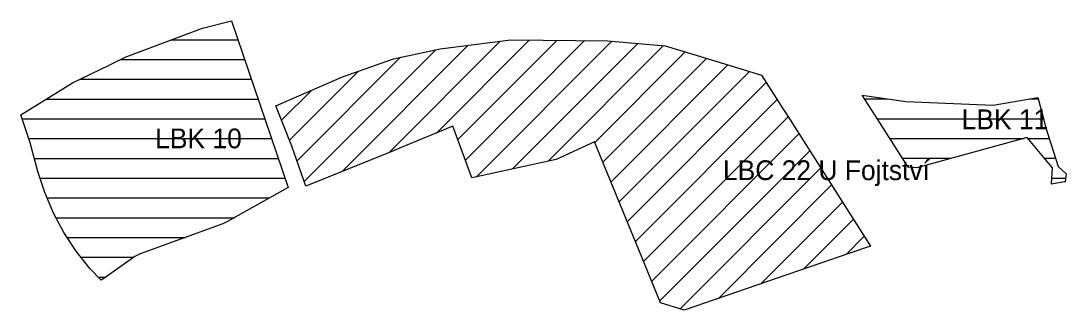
# Model space of a CAD drawing. Extents: x -477054 to -472307, y -1158904 to -1149471.
# Drawn here: x -476516 to -476092.7, y -1154894.3 to -1154777.4 of the extents above; entities that cross this region are included whole.
import ezdxf

# ---------------------------------------------------------------- set-up
doc = ezdxf.new("R2010")
doc.units = 0
doc.layers.add('16', color=7, linetype='Continuous')
doc.layers.add('19', color=7, linetype='Continuous')

msp = doc.modelspace()

# ---------------------------------------------------------------- linework, layer by layer
at = {"layer": '16'}
for p, q in [((-476454.84, -1154784.97), (-476428.16, -1154784.97)), ((-476385.77, -1154838.19), (-476334.82, -1154787.24)), ((-476366.82, -1154830.56), (-476321.87, -1154785.61)), ((-476347.69, -1154822.74), (-476310.09, -1154785.14)), ((-476339.04, -1154825.4), (-476298.88, -1154785.25)), ((-476335.99, -1154833.68), (-476287.68, -1154785.36)), ((-476331.41, -1154840.41), (-476276.6, -1154785.6)), ((-476316.95, -1154837.26), (-476266.19, -1154786.49)), ((-476302.49, -1154834.12), (-476255.77, -1154787.39)), ((-476475.57, -1154792.97), (-476425.43, -1154792.97)), ((-476404.15, -1154833.95), (-476362.28, -1154792.08)), ((-476401.22, -1154842.33), (-476347.93, -1154789.04)), ((-476283.61, -1154826.54), (-476246.98, -1154789.92)), ((-476280.31, -1154834.56), (-476238.3, -1154792.55)), ((-476277.01, -1154842.57), (-476229.62, -1154795.19)), ((-476492.11, -1154800.97), (-476422.69, -1154800.97)), ((-476407.17, -1154825.65), (-476379.22, -1154797.71)), ((-476273.71, -1154850.58), (-476220.94, -1154797.82)), ((-476410.38, -1154817.55), (-476398.29, -1154805.46)), ((-476270.41, -1154858.6), (-476214.13, -1154802.32)), ((-476505.64, -1154808.97), (-476419.96, -1154808.97)), ((-476267.11, -1154866.61), (-476209.72, -1154809.22)), ((-476174.31, -1154808.92), (-476165.01, -1154808.92)), ((-476107.36, -1154808.92), (-476103.97, -1154808.92)), ((-476515.47, -1154816.97), (-476417.23, -1154816.97)), ((-476263.8, -1154874.62), (-476205.31, -1154816.12)), ((-476169.19, -1154816.92), (-476101.86, -1154816.92)), ((-476512.85, -1154824.97), (-476414.49, -1154824.97)), ((-476260.5, -1154882.64), (-476200.89, -1154823.02)), ((-476164.08, -1154824.92), (-476109.68, -1154824.92)), ((-476108.14, -1154824.92), (-476099.51, -1154824.92)), ((-476257.2, -1154890.65), (-476196.48, -1154829.93)), ((-476510.56, -1154832.97), (-476411.76, -1154832.97)), ((-476158.97, -1154832.92), (-476139.04, -1154832.92)), ((-476101.46, -1154832.92), (-476096.99, -1154832.92)), ((-476249.04, -1154893.8), (-476192.07, -1154836.83)), ((-476508.23, -1154840.97), (-476409.03, -1154840.97)), ((-476233.51, -1154889.58), (-476187.66, -1154843.73)), ((-476098.49, -1154840.92), (-476092.85, -1154840.92)), ((-476505.41, -1154848.97), (-476415.26, -1154848.97)), ((-476216.27, -1154883.66), (-476183.25, -1154850.63)), ((-476501.78, -1154856.97), (-476429.5, -1154856.97)), ((-476199.04, -1154877.74), (-476178.83, -1154857.53)), ((-476497.23, -1154864.97), (-476449.49, -1154864.97)), ((-476181.8, -1154871.81), (-476174.42, -1154864.44)), ((-476491.61, -1154872.97), (-476470.28, -1154872.97)), ((-476484.68, -1154880.97), (-476481.64, -1154880.97))]:
    msp.add_line(p, q, dxfattribs=at)
msp.add_lwpolyline([(-476206.39, -1154814.43), (-476199.07, -1154825.88), (-476171.86, -1154868.44), (-476180.31, -1154871.3), (-476247.31, -1154894.32), (-476256.89, -1154891.41), (-476265.75, -1154869.9), (-476283.71, -1154826.29), (-476299.16, -1154833.39), (-476332.67, -1154840.68), (-476333.37, -1154840.83), (-476333.52, -1154840.41), (-476341.02, -1154820), (-476362.02, -1154828.63), (-476365.75, -1154830.13), (-476400.58, -1154844.16), (-476406.23, -1154828.01), (-476412.7, -1154811.69), (-476385.68, -1154800.01), (-476365.13, -1154792.68), (-476346.21, -1154788.68), (-476317.58, -1154785.07), (-476278.3, -1154785.45), (-476255.11, -1154787.45), (-476236.24, -1154793.18), (-476216.06, -1154799.3), (-476207.29, -1154813.01)], close=True, dxfattribs=at)
at = {"layer": '19'}
for points in [[(-476483.51, -1154882.18), (-476488.01, -1154877.48), (-476493.6, -1154870.47), (-476498.55, -1154862.98), (-476502.8, -1154855.08), (-476506.32, -1154846.83), (-476509.1, -1154838.27), (-476512.29, -1154826.7), (-476515.98, -1154815.4), (-476495.09, -1154802.41), (-476480.25, -1154795.23), (-476473.76, -1154792.09), (-476442.39, -1154780.28), (-476430.75, -1154777.39), (-476407.74, -1154844.74), (-476432.57, -1154858.69), (-476434.16, -1154859.42), (-476467.74, -1154871.57), (-476469.85, -1154872.67), (-476482.4, -1154881.5)], [(-476157.56, -1154809.98), (-476122.25, -1154811.42), (-476104.11, -1154808.37), (-476101.89, -1154816.8), (-476101.12, -1154819.73), (-476100.98, -1154820.24), (-476095.94, -1154836.24), (-476092.69, -1154839.28), (-476093, -1154842.52), (-476093.41, -1154842.45), (-476098.66, -1154843.43), (-476098.22, -1154836.78), (-476099.05, -1154835.8), (-476108.42, -1154824.57), (-476153.16, -1154836.77), (-476156.61, -1154836.59), (-476169.2, -1154816.91), (-476175.24, -1154807.46)]]:
    msp.add_lwpolyline(points, close=True, dxfattribs=at)

# ---------------------------------------------------------------- texts
at = {"layer": '16'}
msp.add_text('LBC 22 U Fojtství', height=8, dxfattribs=at).set_placement((-476231.65, -1154841.76))
at = {"layer": '19'}
for s, p in [('LBK 11', (-476134.99, -1154821.18)), ('LBK 10', (-476461.6, -1154828.9))]:
    msp.add_text(s, height=8, dxfattribs=at).set_placement(p)

doc.saveas('drawing.dxf')
